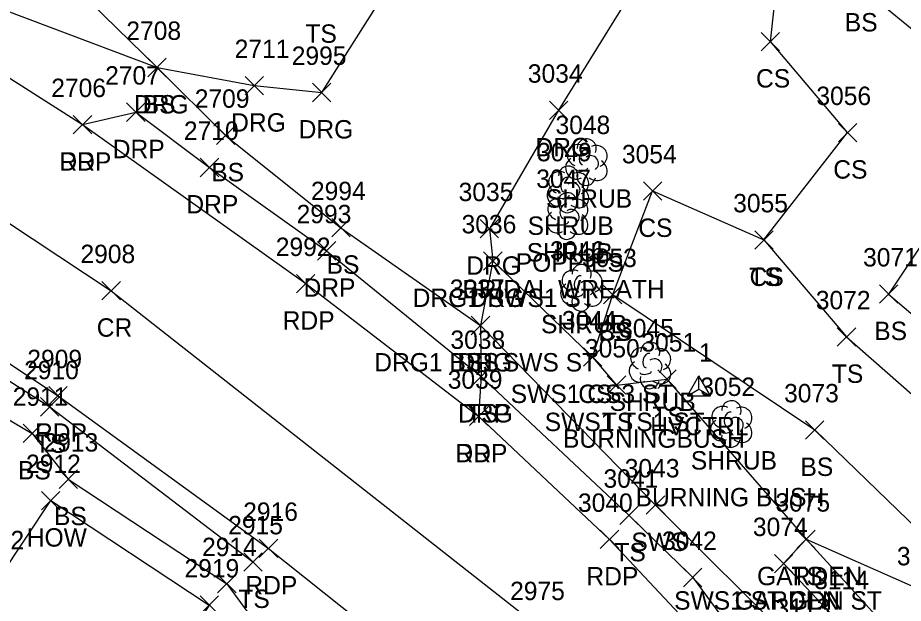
# Model space of a CAD drawing. Extents: x 1499292 to 1501024, y 534584 to 538043.
# Drawn here: x 1499718.2 to 1499814.4, y 537733.8 to 537797.5 of the extents above; entities that cross this region are included whole.
import ezdxf

# ---------------------------------------------------------------- set-up
doc = ezdxf.new("R2010")
doc.units = 0
for name, color, linetype in [('C_A', 7, 'Continuous'), ('C_I', 7, 'Continuous'), ('CPSM', 7, 'Continuous'), ('L_A', 7, 'Continuous'), ('L_C', 7, 'Continuous'), ('L_I', 7, 'Continuous'), ('L_TIC', 7, 'Continuous'), ('LAPB', 7, 'Continuous'), ('LBC', 7, 'Continuous'), ('LELB', 7, 'Continuous'), ('LSH', 7, 'Continuous'), ('P_A', 7, 'Continuous'), ('P_I', 7, 'Continuous'), ('P_TIC', 7, 'Continuous'), ('PET', 7, 'Continuous'), ('PRC', 7, 'Continuous'), ('R_A', 7, 'Continuous'), ('R_I', 7, 'Continuous'), ('R_TIC', 7, 'Continuous'), ('RDG', 7, 'Continuous'), ('RDP', 7, 'Continuous'), ('RGR', 7, 'Continuous'), ('RSW', 7, 'Continuous')]:
    doc.layers.add(name, color=color, linetype=linetype)

msp = doc.modelspace()

# ---------------------------------------------------------------- linework, layer by layer
at = {"layer": 'CPSM'}
for p, q in [((1499790.956, 537756.384), (1499792.206, 537758.549)), ((1499793.456, 537756.384), (1499792.206, 537758.549)), ((1499792.206, 537757.105), (1499792.206, 537758.549)), ((1499790.956, 537756.384), (1499792.206, 537757.105)), ((1499790.956, 537756.384), (1499793.456, 537756.384)), ((1499792.206, 537757.105), (1499792.206, 537757.105)), ((1499792.206, 537757.105), (1499793.456, 537756.384))]:
    msp.add_line(p, q, dxfattribs=at)
at = {"layer": 'L_TIC'}
for points in [[(1499798.962, 537793.899), (1499800.962, 537795.899)], [(1499800.962, 537793.899), (1499798.962, 537795.899)], [(1499732.304, 537791.08), (1499734.304, 537793.08)], [(1499734.304, 537791.08), (1499732.304, 537793.08)], [(1499739.748, 537783.702), (1499741.748, 537785.702)], [(1499741.748, 537783.702), (1499739.748, 537785.702)], [(1499807.361, 537783.999), (1499809.361, 537785.999)], [(1499809.361, 537783.999), (1499807.361, 537785.999)], [(1499786.168, 537777.661), (1499788.168, 537779.661)], [(1499788.168, 537777.661), (1499786.168, 537779.661)], [(1499752.291, 537773.66), (1499754.291, 537775.66)], [(1499754.291, 537773.66), (1499752.291, 537775.66)], [(1499798.262, 537772.333), (1499800.262, 537774.333)], [(1499800.262, 537772.333), (1499798.262, 537774.333)], [(1499798.262, 537772.333), (1499800.262, 537774.333)], [(1499800.262, 537772.333), (1499798.262, 537774.333)], [(1499798.262, 537772.333), (1499800.262, 537774.333)], [(1499800.262, 537772.333), (1499798.262, 537774.333)], [(1499781.834, 537766.387), (1499783.834, 537768.387)], [(1499783.834, 537766.387), (1499781.834, 537768.387)], [(1499781.834, 537766.387), (1499783.834, 537768.387)], [(1499783.834, 537766.387), (1499781.834, 537768.387)], [(1499811.815, 537766.449), (1499813.815, 537768.449)], [(1499813.815, 537766.449), (1499811.815, 537768.449)], [(1499767.462, 537763.036), (1499769.462, 537765.036)], [(1499769.462, 537763.036), (1499767.462, 537765.036)], [(1499807.241, 537761.795), (1499809.241, 537763.795)], [(1499809.241, 537761.795), (1499807.241, 537763.795)], [(1499779.646, 537759.607), (1499781.646, 537761.607)], [(1499781.646, 537759.607), (1499779.646, 537761.607)], [(1499767.531, 537757.489), (1499769.531, 537759.489)], [(1499769.531, 537757.489), (1499767.531, 537759.489)], [(1499787.722, 537757.202), (1499789.722, 537759.202)], [(1499789.722, 537757.202), (1499787.722, 537759.202)], [(1499782.242, 537756.557), (1499784.242, 537758.557)], [(1499784.242, 537756.557), (1499782.242, 537758.557)], [(1499720.632, 537754.195), (1499722.632, 537756.195)], [(1499722.632, 537754.195), (1499720.632, 537756.195)], [(1499718.743, 537751.304), (1499720.743, 537753.304)], [(1499720.743, 537751.304), (1499718.743, 537753.304)], [(1499803.794, 537751.679), (1499805.794, 537753.679)], [(1499805.794, 537751.679), (1499803.794, 537753.679)], [(1499722.657, 537746.33), (1499724.657, 537748.33)], [(1499724.657, 537746.33), (1499722.657, 537748.33)], [(1499720.755, 537743.999), (1499722.755, 537745.999)], [(1499722.755, 537743.999), (1499720.755, 537745.999)], [(1499783.6, 537742.399), (1499785.6, 537744.399)], [(1499785.6, 537742.399), (1499783.6, 537744.399)], [(1499802.85, 537739.802), (1499804.85, 537741.802)], [(1499804.85, 537739.802), (1499802.85, 537741.802)], [(1499802.85, 537739.802), (1499804.85, 537741.802)], [(1499804.85, 537739.802), (1499802.85, 537741.802)], [(1499742.729, 537737.33), (1499744.729, 537739.33)], [(1499744.729, 537737.33), (1499742.729, 537739.33)], [(1499800.405, 537737.147), (1499802.405, 537739.147)], [(1499802.405, 537737.147), (1499800.405, 537739.147)], [(1499739.89, 537734.965), (1499741.89, 537736.965)], [(1499741.89, 537734.965), (1499739.89, 537736.965)], [(1499790.527, 537735.644), (1499792.527, 537737.644)], [(1499792.527, 537735.644), (1499790.527, 537737.644)], [(1499737.986, 537732.643), (1499739.986, 537734.643)], [(1499739.986, 537732.643), (1499737.986, 537734.643)]]:
    msp.add_lwpolyline(points, dxfattribs=at)
at = {"layer": 'LAPB'}
msp.add_lwpolyline([(1499801.405, 537738.147), (1499803.85, 537740.802), (1499817.054, 537734.964), (1499826.976, 537731.369), (1499832.072, 537725.788), (1499830.067, 537721.188), (1499824.291, 537718.43), (1499822.437, 537716.533)], dxfattribs=at)
at = {"layer": 'LBC'}
msp.add_lwpolyline([(1499697.587, 537727.89), (1499690.115, 537732.638), (1499693.073, 537737.884), (1499694.333, 537739.703), (1499698.305, 537745.626), (1499698.593, 537746.054), (1499699.211, 537747.217), (1499705.404, 537743.454), (1499710.54, 537740.083), (1499716.249, 537736.711), (1499721.755, 537744.999), (1499738.986, 537733.643), (1499732.104, 537722.822), (1499729.121, 537718.079), (1499724.689, 537711.282), (1499721.272, 537713.245)], dxfattribs=at)
at = {"layer": 'LELB'}
for points in [[(1499627.747, 537855.268), (1499639.004, 537847.929), (1499652.639, 537838.691), (1499667.661, 537835.904), (1499684.96, 537820.495), (1499707.639, 537812.939), (1499721.619, 537803.525), (1499733.304, 537792.08), (1499740.748, 537784.702), (1499753.291, 537774.66), (1499768.462, 537764.036)], [(1499799.262, 537773.333), (1499808.361, 537784.999), (1499799.962, 537794.899), (1499801.405, 537807.798), (1499808.784, 537821.016), (1499822.829, 537835.344), (1499837.599, 537851.954), (1499846.63, 537848.074), (1499861.497, 537834.452)], [(1499911.083, 537815.726), (1499889.765, 537822.063), (1499878.916, 537825.714), (1499862.045, 537824.015), (1499856.273, 537825.787), (1499837.815, 537837.38), (1499818.511, 537817.661), (1499809.614, 537800.995), (1499826.142, 537787.437), (1499812.815, 537767.449), (1499825.677, 537756.513), (1499830.242, 537743.499)], [(1499673.505, 537786.342), (1499677.07, 537783.592), (1499700.821, 537763.481), (1499719.743, 537752.304), (1499723.657, 537747.33), (1499740.89, 537735.965), (1499752.712, 537719.821), (1499760.138, 537714.193), (1499776.543, 537702.52), (1499783.898, 537695.878)], [(1499676.536, 537785.628), (1499703.551, 537766.74), (1499721.632, 537755.195), (1499743.729, 537738.33)], [(1499780.646, 537760.607), (1499782.834, 537767.387), (1499787.168, 537778.661), (1499799.262, 537773.333)], [(1499799.262, 537773.333), (1499808.241, 537762.795), (1499830.242, 537743.499)], [(1499782.834, 537767.387), (1499804.794, 537752.679), (1499818.307, 537739.62), (1499826.976, 537731.369)], [(1499768.531, 537758.489), (1499784.6, 537743.399), (1499791.527, 537736.644)], [(1499783.242, 537757.557), (1499788.722, 537758.202), (1499803.85, 537740.802), (1499824.291, 537718.43)]]:
    msp.add_lwpolyline(points, dxfattribs=at)
at = {"layer": 'LSH'}
for p, q in [((1499779.95, 537781.839), (1499779.95, 537781.839)), ((1499779.95, 537781.839), (1499779.95, 537781.839)), ((1499777.948, 537778.882), (1499777.948, 537778.882)), ((1499777.948, 537778.882), (1499777.948, 537778.882)), ((1499777.854, 537775.989), (1499777.854, 537775.989)), ((1499777.854, 537775.989), (1499777.854, 537775.989)), ((1499779.407, 537768.186), (1499779.407, 537768.186)), ((1499779.407, 537768.186), (1499779.407, 537768.186)), ((1499786.864, 537759.748), (1499786.864, 537759.748)), ((1499786.864, 537759.748), (1499786.864, 537759.748)), ((1499795.691, 537753.375), (1499795.691, 537753.375)), ((1499795.691, 537753.375), (1499795.691, 537753.375))]:
    msp.add_line(p, q, dxfattribs=at)
for centre in [(1499779.997, 537783.273), (1499777.994, 537780.316), (1499777.901, 537777.423), (1499779.454, 537769.62), (1499786.911, 537761.182), (1499795.738, 537754.809)]:
    msp.add_arc(centre, 1.047, 335.52715, 180.95627, dxfattribs=at)
for centre, major_axis, ratio, start_param, end_param in [((1499779.158, 537782.505), (1.21, -0.512), 0.895232, 1.570796, 4.712389), ((1499779.742, 537782.297), (-0.208, -0.792), 0.645439, 3.141593, 6.283185), ((1499780.992, 537782.422), (-1.141, -0.483), 0.949671, 1.570796, 4.712389), ((1499778.867, 537781.13), (0.584, -1.042), 0.959034, 3.141593, 6.283185), ((1499780.45, 537781.672), (-0.5, 0.667), 0.989748, 3.141593, 6.283185), ((1499780.95, 537781.006), (-1.09, 0.792), 0.841452, 1.570796, 4.712389), ((1499777.156, 537779.548), (1.21, -0.512), 0.895232, 1.570796, 4.712389), ((1499778.989, 537779.465), (-1.141, -0.483), 0.949671, 1.570796, 4.712389), ((1499779.95, 537780.339), (0.265, 1.061), 0.942809, 1.570796, 4.712389), ((1499779.492, 537781.089), (-0.625, -0.083), 0.423636, 0, 3.141593), ((1499777.739, 537779.34), (-0.208, -0.792), 0.645439, 3.141593, 6.283185), ((1499778.448, 537778.715), (-0.5, 0.667), 0.989748, 3.141593, 6.283185), ((1499776.864, 537778.173), (0.584, -1.042), 0.959034, 3.141593, 6.283185), ((1499778.948, 537778.048), (-1.09, 0.792), 0.841452, 1.570796, 4.712389), ((1499777.063, 537776.655), (1.21, -0.512), 0.895232, 1.570796, 4.712389), ((1499777.948, 537777.382), (0.265, 1.061), 0.942809, 1.570796, 4.712389), ((1499777.489, 537778.131), (-0.625, -0.083), 0.423636, 0, 3.141593), ((1499778.896, 537776.572), (-1.141, -0.483), 0.949671, 1.570796, 4.712389), ((1499777.646, 537776.447), (-0.208, -0.792), 0.645439, 3.141593, 6.283185), ((1499778.354, 537775.822), (-0.5, 0.667), 0.989748, 3.141593, 6.283185), ((1499776.771, 537775.28), (0.584, -1.042), 0.959034, 3.141593, 6.283185), ((1499778.855, 537775.155), (-1.09, 0.792), 0.841452, 1.570796, 4.712389), ((1499777.855, 537774.489), (0.265, 1.061), 0.942809, 1.570796, 4.712389), ((1499777.396, 537775.239), (-0.625, -0.083), 0.423636, 0, 3.141593), ((1499778.615, 537768.853), (1.21, -0.512), 0.895232, 1.570796, 4.712389), ((1499780.448, 537768.77), (-1.141, -0.483), 0.949671, 1.570796, 4.712389), ((1499779.198, 537768.644), (-0.208, -0.792), 0.645439, 3.141593, 6.283185), ((1499779.907, 537768.02), (-0.5, 0.667), 0.989748, 3.141593, 6.283185), ((1499778.324, 537767.478), (0.584, -1.042), 0.959034, 3.141593, 6.283185), ((1499780.407, 537767.353), (-1.09, 0.792), 0.841452, 1.570796, 4.712389), ((1499779.407, 537766.686), (0.265, 1.061), 0.942809, 1.570796, 4.712389), ((1499778.949, 537767.436), (-0.625, -0.083), 0.423636, 0, 3.141593), ((1499786.072, 537760.415), (1.21, -0.512), 0.895232, 1.570796, 4.712389), ((1499786.656, 537760.206), (-0.208, -0.792), 0.645439, 3.141593, 6.283185), ((1499787.906, 537760.332), (-1.141, -0.483), 0.949671, 1.570796, 4.712389), ((1499785.781, 537759.04), (0.584, -1.042), 0.959034, 3.141593, 6.283185), ((1499787.364, 537759.581), (-0.5, 0.667), 0.989748, 3.141593, 6.283185), ((1499786.406, 537758.998), (-0.625, -0.083), 0.423636, 0, 3.141593), ((1499787.864, 537758.915), (-1.09, 0.792), 0.841452, 1.570796, 4.712389), ((1499786.864, 537758.248), (0.265, 1.061), 0.942809, 1.570796, 4.712389), ((1499794.899, 537754.042), (1.21, -0.512), 0.895232, 1.570796, 4.712389), ((1499796.732, 537753.959), (-1.141, -0.483), 0.949671, 1.570796, 4.712389), ((1499795.482, 537753.833), (-0.208, -0.792), 0.645439, 3.141593, 6.283185), ((1499794.608, 537752.667), (0.584, -1.042), 0.959034, 3.141593, 6.283185), ((1499796.191, 537753.209), (-0.5, 0.667), 0.989748, 3.141593, 6.283185), ((1499796.691, 537752.542), (-1.09, 0.792), 0.841452, 1.570796, 4.712389), ((1499795.233, 537752.625), (-0.625, -0.083), 0.423636, 0, 3.141593), ((1499795.691, 537751.875), (0.265, 1.061), 0.942809, 1.570796, 4.712389)]:
    msp.add_ellipse(centre, major_axis=major_axis, ratio=ratio, start_param=start_param, end_param=end_param, dxfattribs=at)
at = {"layer": 'P_TIC'}
for points in [[(1499724.198, 537784.865), (1499726.198, 537786.865)], [(1499726.198, 537784.865), (1499724.198, 537786.865)], [(1499727.317, 537766.815), (1499729.317, 537768.815)], [(1499729.317, 537766.815), (1499727.317, 537768.815)], [(1499748.466, 537767.587), (1499750.466, 537769.587)], [(1499750.466, 537767.587), (1499748.466, 537769.587)], [(1499721.55, 537755.398), (1499723.55, 537757.398)], [(1499723.55, 537755.398), (1499721.55, 537757.398)], [(1499767.247, 537753.161), (1499769.247, 537755.161)], [(1499769.247, 537753.161), (1499767.247, 537755.161)], [(1499781.48, 537739.777), (1499783.48, 537741.777)], [(1499783.48, 537739.777), (1499781.48, 537741.777)], [(1499744.414, 537738.8), (1499746.414, 537740.8)], [(1499746.414, 537738.8), (1499744.414, 537740.8)]]:
    msp.add_lwpolyline(points, dxfattribs=at)
at = {"layer": 'PET'}
for points in [[(1499318.777, 538007.185), (1499356.077, 537991.329), (1499396.207, 537971.039), (1499437.012, 537950.167), (1499476.074, 537929.172), (1499509.306, 537910.677), (1499546.423, 537890.59), (1499566.293, 537879.272), (1499602.082, 537858.76), (1499615.195, 537851.418), (1499643.027, 537835.063), (1499676.234, 537815.623), (1499707.101, 537797.403), (1499725.198, 537785.865), (1499749.466, 537768.587), (1499768.247, 537754.161), (1499782.48, 537740.777), (1499805.279, 537716.472), (1499820.533, 537699.08)], [(1499310.023, 537983.746), (1499343.075, 537969.541), (1499383.731, 537949.439), (1499427.71, 537927.425), (1499464.171, 537907.983), (1499500.199, 537887.497), (1499544.495, 537863.142), (1499587.74, 537838.677), (1499616.247, 537822.183), (1499651.021, 537801.554), (1499676.536, 537785.628), (1499704.158, 537768.574), (1499722.55, 537756.398), (1499745.414, 537739.8), (1499767.298, 537722.36), (1499790.892, 537701.646), (1499806.057, 537686.036), (1499813.912, 537693.068), (1499820.533, 537699.08)]]:
    msp.add_lwpolyline(points, dxfattribs=at)
at = {"layer": 'PRC'}
msp.add_lwpolyline([(1499314.647, 537995.238), (1499351.896, 537980.059), (1499390.853, 537960.785), (1499432.771, 537938.063), (1499470.255, 537918.917), (1499503.529, 537899.736), (1499550.301, 537873.589), (1499594.281, 537849.334), (1499631.071, 537828.01), (1499665.93, 537807.267), (1499699.614, 537786.782), (1499728.317, 537767.815), (1499774.937, 537731.181), (1499796.918, 537710.716), (1499813.912, 537693.068)], dxfattribs=at)
at = {"layer": 'R_TIC'}
for points in [[(1499732.304, 537791.08), (1499734.304, 537793.08)], [(1499734.304, 537791.08), (1499732.304, 537793.08)], [(1499742.867, 537789.105), (1499744.867, 537791.105)], [(1499744.867, 537789.105), (1499742.867, 537791.105)], [(1499750.203, 537788.361), (1499752.203, 537790.361)], [(1499752.203, 537788.361), (1499750.203, 537790.361)], [(1499729.999, 537786.221), (1499731.999, 537788.221)], [(1499731.999, 537786.221), (1499729.999, 537788.221)], [(1499775.944, 537786.425), (1499777.944, 537788.425)], [(1499777.944, 537786.425), (1499775.944, 537788.425)], [(1499724.198, 537784.865), (1499726.198, 537786.865)], [(1499726.198, 537784.865), (1499724.198, 537786.865)], [(1499738.001, 537780.211), (1499740.001, 537782.211)], [(1499740.001, 537780.211), (1499738.001, 537782.211)], [(1499768.42, 537773.551), (1499770.42, 537775.551)], [(1499770.42, 537773.551), (1499768.42, 537775.551)], [(1499750.735, 537771.15), (1499752.735, 537773.15)], [(1499752.735, 537771.15), (1499750.735, 537773.15)], [(1499768.797, 537770.048), (1499770.797, 537772.048)], [(1499770.797, 537770.048), (1499768.797, 537772.048)], [(1499768.797, 537770.048), (1499770.797, 537772.048)], [(1499770.797, 537770.048), (1499768.797, 537772.048)], [(1499767.462, 537763.036), (1499769.462, 537765.036)], [(1499769.462, 537763.036), (1499767.462, 537765.036)], [(1499767.462, 537763.036), (1499769.462, 537765.036)], [(1499769.462, 537763.036), (1499767.462, 537765.036)], [(1499779.646, 537759.607), (1499781.646, 537761.607)], [(1499781.646, 537759.607), (1499779.646, 537761.607)], [(1499767.531, 537757.489), (1499769.531, 537759.489)], [(1499769.531, 537757.489), (1499767.531, 537759.489)], [(1499767.531, 537757.489), (1499769.531, 537759.489)], [(1499769.531, 537757.489), (1499767.531, 537759.489)], [(1499782.242, 537756.557), (1499784.242, 537758.557)], [(1499784.242, 537756.557), (1499782.242, 537758.557)], [(1499767.247, 537753.161), (1499769.247, 537755.161)], [(1499769.247, 537753.161), (1499767.247, 537755.161)], [(1499786.478, 537743.52), (1499788.478, 537745.52)], [(1499788.478, 537743.52), (1499786.478, 537745.52)], [(1499800.405, 537737.147), (1499802.405, 537739.147)], [(1499802.405, 537737.147), (1499800.405, 537739.147)], [(1499790.527, 537735.644), (1499792.527, 537737.644)], [(1499792.527, 537735.644), (1499790.527, 537737.644)]]:
    msp.add_lwpolyline(points, dxfattribs=at)
at = {"layer": 'RDG'}
msp.add_lwpolyline([(1499709.457, 537801.089), (1499733.304, 537792.08), (1499743.867, 537790.105), (1499751.203, 537789.361), (1499760.905, 537804.652), (1499770.068, 537817.715), (1499787.094, 537803.859), (1499776.944, 537787.425), (1499769.42, 537774.551), (1499769.797, 537771.048), (1499768.462, 537764.036), (1499768.531, 537758.489)], dxfattribs=at)
at = {"layer": 'RDP'}
msp.add_lwpolyline([(1499725.198, 537785.865), (1499730.999, 537787.221), (1499739.001, 537781.211), (1499751.735, 537772.15), (1499768.531, 537758.489), (1499768.247, 537754.161)], dxfattribs=at)
at = {"layer": 'RGR'}
msp.add_lwpolyline([(1499791.527, 537736.644), (1499806.435, 537716.422), (1499820.783, 537699.42)], dxfattribs=at)
at = {"layer": 'RSW'}
for points in [[(1499769.797, 537771.048), (1499780.646, 537760.607), (1499783.242, 537757.557)], [(1499768.462, 537764.036), (1499787.478, 537744.52), (1499802.653, 537729.359), (1499818.109, 537712.395)], [(1499801.405, 537738.147), (1499806.852, 537732.371), (1499814.574, 537724.992), (1499822.437, 537716.533), (1499818.109, 537712.395)]]:
    msp.add_lwpolyline(points, dxfattribs=at)

# ---------------------------------------------------------------- texts
at = {"layer": 'C_A'}
msp.add_text('HVCTRL', height=2, dxfattribs=at).set_placement((1499786.899, 537752.105))
at = {"layer": 'C_I'}
msp.add_text('1', height=2, dxfattribs=at).set_placement((1499792.206, 537760.105))
at = {"layer": 'L_A'}
for s, p in [('BS', (1499808.055, 537795.995)), ('TS', (1499749.43, 537794.763)), ('CS', (1499798.403, 537789.899)), ('BS', (1499731.745, 537787.08)), ('BS', (1499739.189, 537779.702)), ('CS', (1499806.802, 537779.999)), ('SHRUB', (1499775.58, 537776.839)), ('SHRUB', (1499773.578, 537773.882)), ('CS', (1499785.609, 537773.661)), ('SHRUB', (1499773.484, 537770.989)), ('BS', (1499751.732, 537769.66)), ('TS', (1499797.672, 537768.333)), ('CS', (1499797.703, 537768.333)), ('CS', (1499797.703, 537768.333)), ('SHRUB', (1499775.037, 537763.186)), ('CS', (1499781.275, 537762.387)), ('BS', (1499781.275, 537762.387)), ('BS', (1499811.256, 537762.449)), ('BS', (1499766.903, 537759.036)), ('TS', (1499806.65, 537757.795)), ('CS', (1499779.087, 537755.607)), ('SHRUB', (1499782.494, 537754.748)), ('TS', (1499766.94, 537753.489)), ('TS', (1499787.131, 537753.202)), ('TS', (1499781.652, 537752.557)), ('TS', (1499720.041, 537750.195)), ('SHRUB', (1499791.321, 537748.375)), ('BS', (1499803.235, 537747.679)), ('BS', (1499718.184, 537747.304)), ('BS', (1499722.098, 537742.33)), ('HOW', (1499719.141, 537739.999)), ('TS', (1499783.01, 537738.399)), ('GARDEN', (1499798.52, 537735.802)), ('TS', (1499802.26, 537735.802)), ('TS', (1499742.138, 537733.33)), ('GARDEN', (1499796.075, 537733.147))]:
    msp.add_text(s, height=2, dxfattribs=at).set_placement(p)
at = {"layer": 'L_C'}
for s, p in [('POPPIES', (1499772.294, 537769.882)), ('BRIDAL WREATH', (1499766.484, 537766.989)), ('BURNINGBUSH', (1499777.431, 537750.748)), ('BURNING BUSH', (1499785.313, 537744.375))]:
    msp.add_text(s, height=2, dxfattribs=at).set_placement(p)
at = {"layer": 'L_I'}
for s, p in [('2708', (1499729.965, 537795.08)), ('3056', (1499804.967, 537787.999)), ('2709', (1499737.401, 537787.702)), ('3048', (1499776.612, 537784.839)), ('3049', (1499774.601, 537781.882)), ('3054', (1499783.829, 537781.661)), ('3047', (1499774.516, 537778.989)), ('2994', (1499750.031, 537777.66)), ('3055', (1499795.924, 537776.333)), ('3055', (1499795.924, 537776.333)), ('3055', (1499795.924, 537776.333)), ('3046', (1499776.013, 537771.186)), ('3053', (1499779.496, 537770.387)), ('3053', (1499779.496, 537770.387)), ('3071', (1499810.043, 537770.449)), ('3037', (1499765.124, 537767.036)), ('3072', (1499804.902, 537765.795)), ('3044', (1499777.307, 537763.607)), ('3045', (1499783.526, 537762.748)), ('3038', (1499765.192, 537761.489)), ('3051', (1499785.95, 537761.202)), ('3050', (1499779.817, 537760.557)), ('2910', (1499718.852, 537758.195)), ('3052', (1499792.352, 537756.375)), ('2911', (1499717.617, 537755.304)), ('3073', (1499801.456, 537755.679)), ('2913', (1499720.964, 537750.33)), ('2912', (1499719.062, 537747.999)), ('3041', (1499781.829, 537746.399)), ('3075', (1499800.512, 537743.802)), ('3075', (1499800.512, 537743.802)), ('2915', (1499741.036, 537741.33)), ('3074', (1499798.067, 537741.147)), ('2902', (1499712.91, 537739.711)), ('2914', (1499738.197, 537738.965)), ('3042', (1499788.188, 537739.644)), ('3088', (1499813.715, 537737.964)), ('2919', (1499736.285, 537736.643))]:
    msp.add_text(s, height=2, dxfattribs=at).set_placement(p)
at = {"layer": 'P_A'}
for s, p in [('RDP', (1499722.686, 537780.865)), ('CR', (1499726.75, 537762.815)), ('RDP', (1499746.955, 537763.587)), ('RDP', (1499720.038, 537751.398)), ('RDP', (1499765.736, 537749.161)), ('RDP', (1499779.968, 537735.777)), ('RDP', (1499742.902, 537734.8))]:
    msp.add_text(s, height=2, dxfattribs=at).set_placement(p)
at = {"layer": 'P_I'}
for s, p in [('2706', (1499721.804, 537788.865)), ('2992', (1499746.207, 537771.587)), ('2908', (1499724.978, 537770.815)), ('2909', (1499719.203, 537759.398)), ('3039', (1499764.901, 537757.161)), ('3040', (1499779.055, 537743.777)), ('2916', (1499742.666, 537742.8)), ('2975', (1499771.677, 537734.181))]:
    msp.add_text(s, height=2, dxfattribs=at).set_placement(p)
at = {"layer": 'R_A'}
for s, p in [('DRG', (1499730.792, 537787.08)), ('DRG', (1499741.355, 537785.105)), ('DRG', (1499748.691, 537784.361)), ('DRP', (1499728.487, 537782.221)), ('DRG', (1499774.432, 537782.425)), ('DRP', (1499722.686, 537780.865)), ('DRP', (1499736.489, 537776.211)), ('DRG', (1499766.908, 537769.551)), ('DRP', (1499749.223, 537767.15)), ('DRG1 SWS1 ST', (1499761.081, 537766.048)), ('DRG', (1499767.285, 537766.048)), ('DRG1 BS1 SWS ST', (1499756.911, 537759.036)), ('DRG', (1499765.951, 537759.036)), ('SWS1 CS3 ST', (1499771.74, 537755.607)), ('DRG', (1499766.019, 537753.489)), ('DRP', (1499766.019, 537753.489)), ('SWS1 TS1 ST', (1499775.439, 537752.557)), ('DRP', (1499765.736, 537749.161)), ('SWS', (1499784.848, 537739.52)), ('SWS1 ST GDN ST', (1499789.508, 537733.147))]:
    msp.add_text(s, height=2, dxfattribs=at).set_placement(p)
at = {"layer": 'R_I'}
for s, p in [('2708', (1499729.965, 537795.08)), ('2711', (1499741.741, 537793.105)), ('2995', (1499747.943, 537792.361)), ('2707', (1499727.66, 537790.221)), ('3034', (1499773.605, 537790.425)), ('2706', (1499721.804, 537788.865)), ('2710', (1499736.221, 537784.211)), ('3035', (1499766.081, 537777.551)), ('2993', (1499748.475, 537775.15)), ('3036', (1499766.404, 537774.048)), ('3036', (1499766.404, 537774.048)), ('3037', (1499765.124, 537767.036)), ('3037', (1499765.124, 537767.036)), ('3044', (1499777.307, 537763.607)), ('3038', (1499765.192, 537761.489)), ('3038', (1499765.192, 537761.489)), ('3050', (1499779.817, 537760.557)), ('3039', (1499764.901, 537757.161)), ('3043', (1499784.139, 537747.52)), ('3074', (1499798.067, 537741.147)), ('3042', (1499788.188, 537739.644)), ('3114', (1499804.726, 537735.371)), ('3113', (1499800.527, 537732.359))]:
    msp.add_text(s, height=2, dxfattribs=at).set_placement(p)

doc.saveas('drawing.dxf')
